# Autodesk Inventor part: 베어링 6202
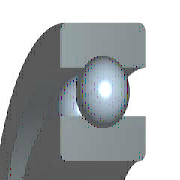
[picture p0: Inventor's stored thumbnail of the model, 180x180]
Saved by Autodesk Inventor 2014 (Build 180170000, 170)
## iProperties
IsCustomPart: 1
Created: 2015-12
Part Number: 베어링 6202
Material: 강철, 연강
Description: 깊은 그루브 볼 베어링
Document SubType Name: Modeling
Standard: KS B 2023
Designer: mdu
Standards Organization: KS
Language: ko-KR
Size Designation: 6202 - 15 x 35 x 11
Categories: <MemberInstance><Categories><Category DisplayName="샤프트 부품" InternalName="7f7aeb1f-a693-4053-b835-cee3144e0d98" Mnemonic="SHFT"><Category DisplayName="베어링" Inter
Density: 7.86 g/cm^3
Mass: 45.8725 g
Surface Area: 51.5584 cm^2
Volume: 5.83619 cm^3
Appearance: 노란색
Author: mdu
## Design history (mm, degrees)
sketch "스케치" dims "d0" = 5.2 (= -0.26 x WD + 0.26 x BD)
  geometry: L1 (2.9, 12.5)-(8.1, 12.5); L2 (5.5, 12.5)-(5.5, 9.9); L3 (5.5, 12.5)-(5.5, 15.1); L4 (3.568, 10.76)-(0, 10.76); L5 (0, 7.5)-(11, 7.5); L6 (3.568, 14.24)-(0, 14.24); L7 (0, 17.5)-(11, 17.5); L8 (11, 7.5)-(11, 10.76); L9 (7.432, 10.76)-(11, 10.76); L10 (7.432, 14.24)-(11, 14.24); L11 (11, 17.5)-(11, 14.24); L12 (-1.4, 0)-(8.4, 0) reference; L13 (0, -0.3)-(0, 5.3) reference
  constraints: 22 end point, 4 point on line, 2 collinear, 2 perpendicular, 2 symmetric about line, 1 midpoint, 1 parallel, 14 other
  dimensions: "d9" = 15 diameter of L5 L12 (= WD); "d11" = 35 diameter of L7 L12 (= BD); "d12" = 11 distance between parallel lines of L8 L13 (= KB); "d13" = 21.52 diameter of L9 L12 (= 0.326 x BD + 0.674 x WD)
revolve "본체" stored, may be unused: angle "d6" = 90 deg
revolve "볼" stored, may be unused: angle "d7" = 90 deg
pattern_circular "IDS_ARRAYBALL[SIMPL:T]" dims angle "d3" = 360 deg
body "Solid1"
fillet "모깎기1" dims "d1" = 0.6 (= KRS)
other parameters: "WD" = 15 [user parameter; used in 5 equation terms], "BD" = 35 [user parameter; used in 5 equation terms], "KB" = 11 [user parameter; used in 1 equation term], "KRS" = 0.6 [user parameter; used in 1 equation term], "d4" = 0, "d5" = 0, "d8" = 0, "d14" = 0, "d15" = 0, "BBA" = 0 [user parameter], "BC0" = 3750000 [user parameter], "BC" = 7800000 [user parameter], "BR" = 17.5 (= 0.5 x BD) [user parameter], "WR" = 7.5 (= 0.5 x WD) [user parameter]
